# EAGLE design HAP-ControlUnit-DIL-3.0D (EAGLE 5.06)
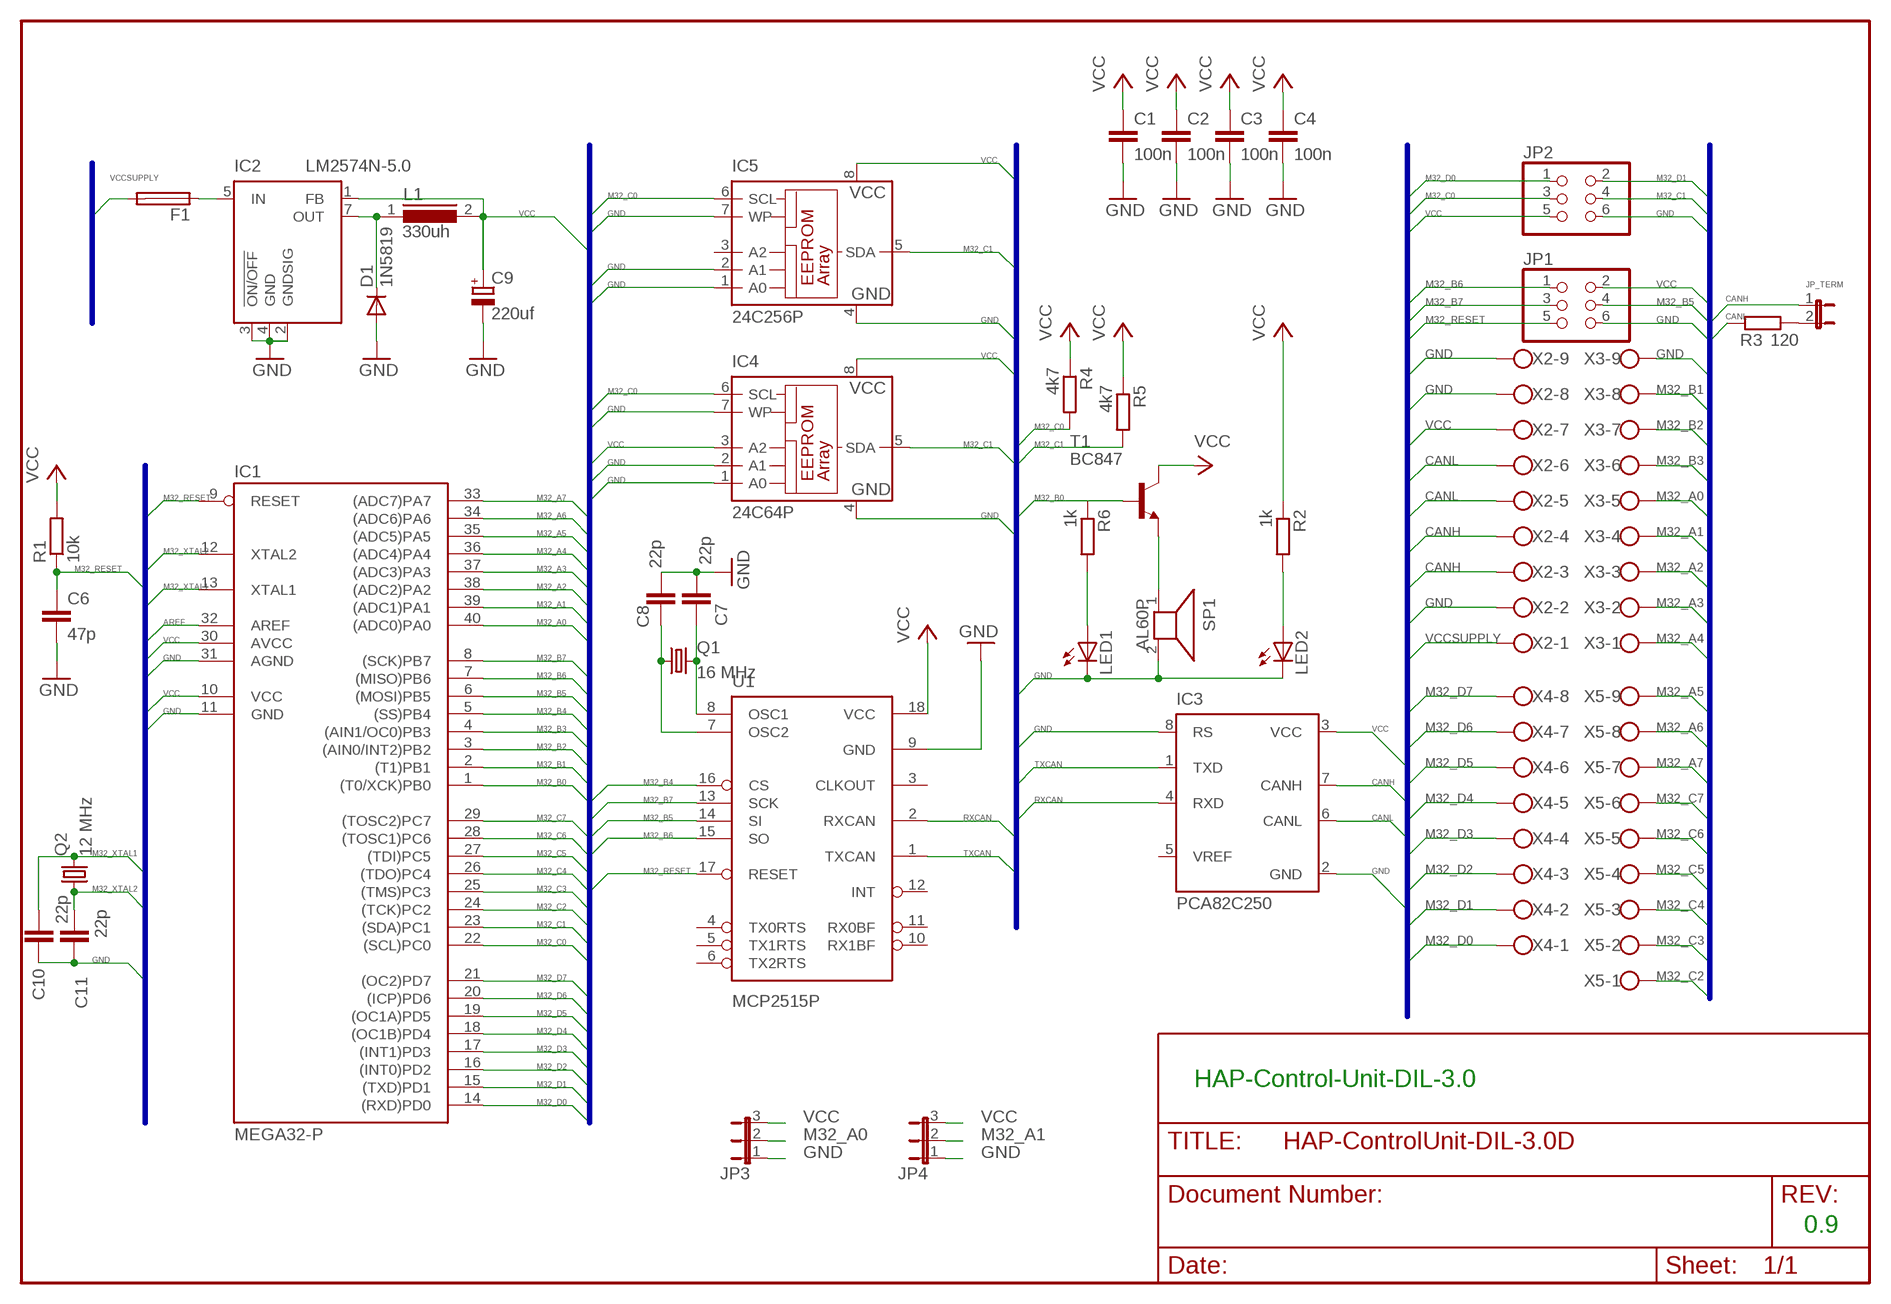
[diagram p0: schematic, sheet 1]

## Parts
C1  100n  C-EUC0805  [C0805]
C2  100n  C-EUC0805  [C0805]
C3  100n  C-EUC0805  [C0805]
C4  100n  C-EUC0805  [C0805]
C6  47p  C-EUC0805  [C0805]
C7  22p  C-EUC0805  [C0805]
C8  22p  C-EUC0805  [C0805]
C9  220uf  CPOL-EUE3.5-8  [E3,5-8]
C10  22p  C-EUC0805  [C0805]
C11  22p  C-EUC0805  [C0805]
D1  1N5819  1N4446  [DO35-10]
F1  TR5  [TR5]
IC1  MEGA32-P  [DIL40]
IC2  LM2574N-5.0  [DIL08]
IC3  PCA82C250  [DIL08]
IC4  24C64P  [DIL8]
IC5  24C256P  24C64P  [DIL8]
JP1  PINHD-2X3  [2X03]
JP2  PINHD-2X3  [2X03]
JP3  JP2E  [JP2]
JP4  JP2E  [JP2]
JP_TERM  JP1E  [JP1]
L1  330uh  82114R  [82114R]
LED1  LED3MM  [LED3MM]
LED2  LED3MM  [LED3MM]
Q1  16 MHz  CRYSTALHC49U70  [HC49U70]
Q2  12 MHz  CRYSTALHC49U70  [HC49U70]
R1  10k  R-EU_R0805  [R0805]
R2  1k  R-EU_R0805  [R0805]
R3  120  R-EU_R0805  [R0805]
R4  4k7  R-EU_R0805  [R0805]
R5  4k7  R-EU_R0805  [R0805]
R6  1k  R-EU_R0805  [R0805]
SP1  AL60P  [AL60P]
T1  BC847  [SOT23]
U1  MCP2515P  MCP2510P  [DIL18]
X2  W237-09P  [W237-9P]
X3  W237-09P  [W237-9P]
X4  W237-08P  [W237-8P]
X5  W237-09P  [W237-9P]

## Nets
AREF: IC1.32(AREF)
CANH: IC3.7(CANH) JP_TERM.1 X2.3 X2.4
CANL: IC3.6(CANL) R3.1 X2.5 X2.6
GND [VCC_GND]: C1.2 C2.2 C3.2 C4.2 C6.2 C7.2 C8.2 C9.- C10.2 C11.1 D1.A IC1.11(GND) IC1.31(AGND) IC2.2(GNDSIG) IC2.3(!ON/OFF) IC2.4(GND) IC3.2(GND) IC3.8(RS) IC4.1(A0) IC4.2(A1) IC4.4(GND) IC4.7(WP) IC5.1(A0) IC5.2(A1) IC5.4(GND) IC5.7(WP) JP1.6 JP2.6 JP3.1 JP4.1 LED1.K(C) LED2.K(C) SP1.2 U1.9(GND) X2.2 X2.8 X2.9 X3.9
M32_A0: IC1.40((ADC0)PA0) JP3.2 X3.5
M32_A1: IC1.39((ADC1)PA1) JP4.2 X3.4
M32_A2: IC1.38((ADC2)PA2) X3.3
M32_A3: IC1.37((ADC3)PA3) X3.2
M32_A4: IC1.36((ADC4)PA4) X3.1
M32_A5: IC1.35((ADC5)PA5) X5.9
M32_A6: IC1.34((ADC6)PA6) X5.8
M32_A7: IC1.33((ADC7)PA7) X5.7
M32_B0: IC1.1((T0/XCK)PB0) R6.1 T1.1(B)
M32_B1: IC1.2((T1)PB1) X3.8
M32_B2: IC1.3((AIN0/INT2)PB2) X3.7
M32_B3: IC1.4((AIN1/OC0)PB3) X3.6
M32_B4: IC1.5((SS)PB4) U1.16(CS)
M32_B5: IC1.6((MOSI)PB5) JP1.4 U1.14(SI)
M32_B6: IC1.7((MISO)PB6) JP1.1 U1.15(SO)
M32_B7: IC1.8((SCK)PB7) JP1.3 U1.13(SCK)
M32_C0: IC1.22((SCL)PC0) IC4.6(SCL) IC5.6(SCL) JP2.3 R4.2
M32_C1: IC1.23((SDA)PC1) IC4.5(SDA) IC5.5(SDA) JP2.4 R5.2
M32_C2: IC1.24((TCK)PC2) X5.1
M32_C3: IC1.25((TMS)PC3) X5.2
M32_C4: IC1.26((TDO)PC4) X5.3
M32_C5: IC1.27((TDI)PC5) X5.4
M32_C6: IC1.28((TOSC1)PC6) X5.5
M32_C7: IC1.29((TOSC2)PC7) X5.6
M32_D0: IC1.14((RXD)PD0) JP2.1 X4.1
M32_D1: IC1.15((TXD)PD1) JP2.2 X4.2
M32_D2: IC1.16((INT0)PD2) X4.3
M32_D3: IC1.17((INT1)PD3) X4.4
M32_D4: IC1.18((OC1B)PD4) X4.5
M32_D5: IC1.19((OC1A)PD5) X4.6
M32_D6: IC1.20((ICP)PD6) X4.7
M32_D7: IC1.21((OC2)PD7) X4.8
M32_RESET: C6.1 IC1.9(RESET) JP1.5 R1.1 U1.17(RESET)
M32_XTAL1: C10.1 IC1.13(XTAL1) Q2.2
M32_XTAL2: C11.2 IC1.12(XTAL2) Q2.1
N$1: LED1.A R6.2
N$2: D1.C IC2.7(OUT) L1.1
N$3: SP1.1 T1.2(E)
N$4: F1.1 IC2.5(IN)
N$5: C7.1 Q1.2 U1.8(OSC1)
N$6: JP_TERM.2 R3.2
N$7: C8.1 Q1.1 U1.7(OSC2)
N$16: LED2.A R2.2
RXCAN: IC3.4(RXD) U1.2(RXCAN)
TXCAN: IC3.1(TXD) U1.1(TXCAN)
VCC [VCC_GND]: C1.1 C2.1 C3.1 C4.1 C9.+ IC1.10(VCC) IC1.30(AVCC) IC2.1(FB) IC3.3(VCC) IC4.3(A2) IC4.8(VCC) IC5.8(VCC) JP1.2 JP2.5 JP3.3 JP4.3 L1.2 R1.2 R2.1 R4.1 R5.1 T1.3(C) U1.18(VCC) X2.7
VCCSUPPLY [VCC_GND]: F1.2 X2.1
Unconnected: IC3.5(VREF) IC5.3(A2) U1.3(CLKOUT) U1.4(TX0RTS) U1.5(TX1RTS) U1.6(TX2RTS) U1.10(RX1BF) U1.11(RX0BF) U1.12(INT)

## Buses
M32_RESET,M32_XTAL2,M32_XTAL1,M32_AREF,M32_AVCC,M32_AGND,M32_A[0..7],M32_B[0..7],M32_C[0..7],M32_D[0..7],VCC,GND,TXCAN,RXCAN,CANH,CANHB,CANL,CANLB,VCCSUPPLY,M32_XTAL1,M32_XTAL2,MCP_OSC1,MCP_OSC2,AREF

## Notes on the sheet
- HAP-Control-Unit-DIL-3.0
- 0.9

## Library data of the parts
C1-C4 C6-C8 C10 C11 = rcl:C-EU: CAPACITOR, European symbol
C9 = rcl:CPOL-EU: POLARIZED CAPACITOR, European symbol
D1 = diode:1N4446: DIODE
F1 = fuse:TR5: FUSE
IC1 = atmel:MEGA32-P: MICROCONTROLLER 32 Kbytes FLASH 2 Kbytes SRAM 1 Kbytes EEPROM USART 8-channel 10 bit ADC Source: www.atmel.com .. doc2503.pdf
IC2 = linear:LM2574?-*: SIMPLE SWITCHER 0.5A Step-Down Voltage Regulator Source: http://cache.national.com/ds/LM/LM2574.pdf
IC3 = micro-philips:PCA82C250: CAN CONTROLLER INTERFACE
IC4 IC5 = microchip:24*: Serial EEPROM I2C
JP1 JP2 = pinhead:PINHD-2X3: PIN HEADER
JP3 JP4 = jumper:JP2E: JUMPER
JP_TERM = jumper:JP1E: JUMPER
L1 = inductors:82114R: INDUCTOR
LED1 LED2 = led:LED: LED
Q1 Q2 = crystal:CRYSTAL: CRYSTAL
R1-R6 = rcl:R-EU_: RESISTOR, European symbol
SP1 = buzzer:AL60P: SPEAKER
T1 = transistor:BC847: NPN TRANSISTOR
U1 = microchip_can:MCP2510
X2 X3 X5 = con-wago-508:W237-09P: WAGO SREW CLAMP
X4 = con-wago-508:W237-08P: WAGO SREW CLAMP

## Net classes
1 VCC_GND: width 0.305 mm, clearance 0.203 mm

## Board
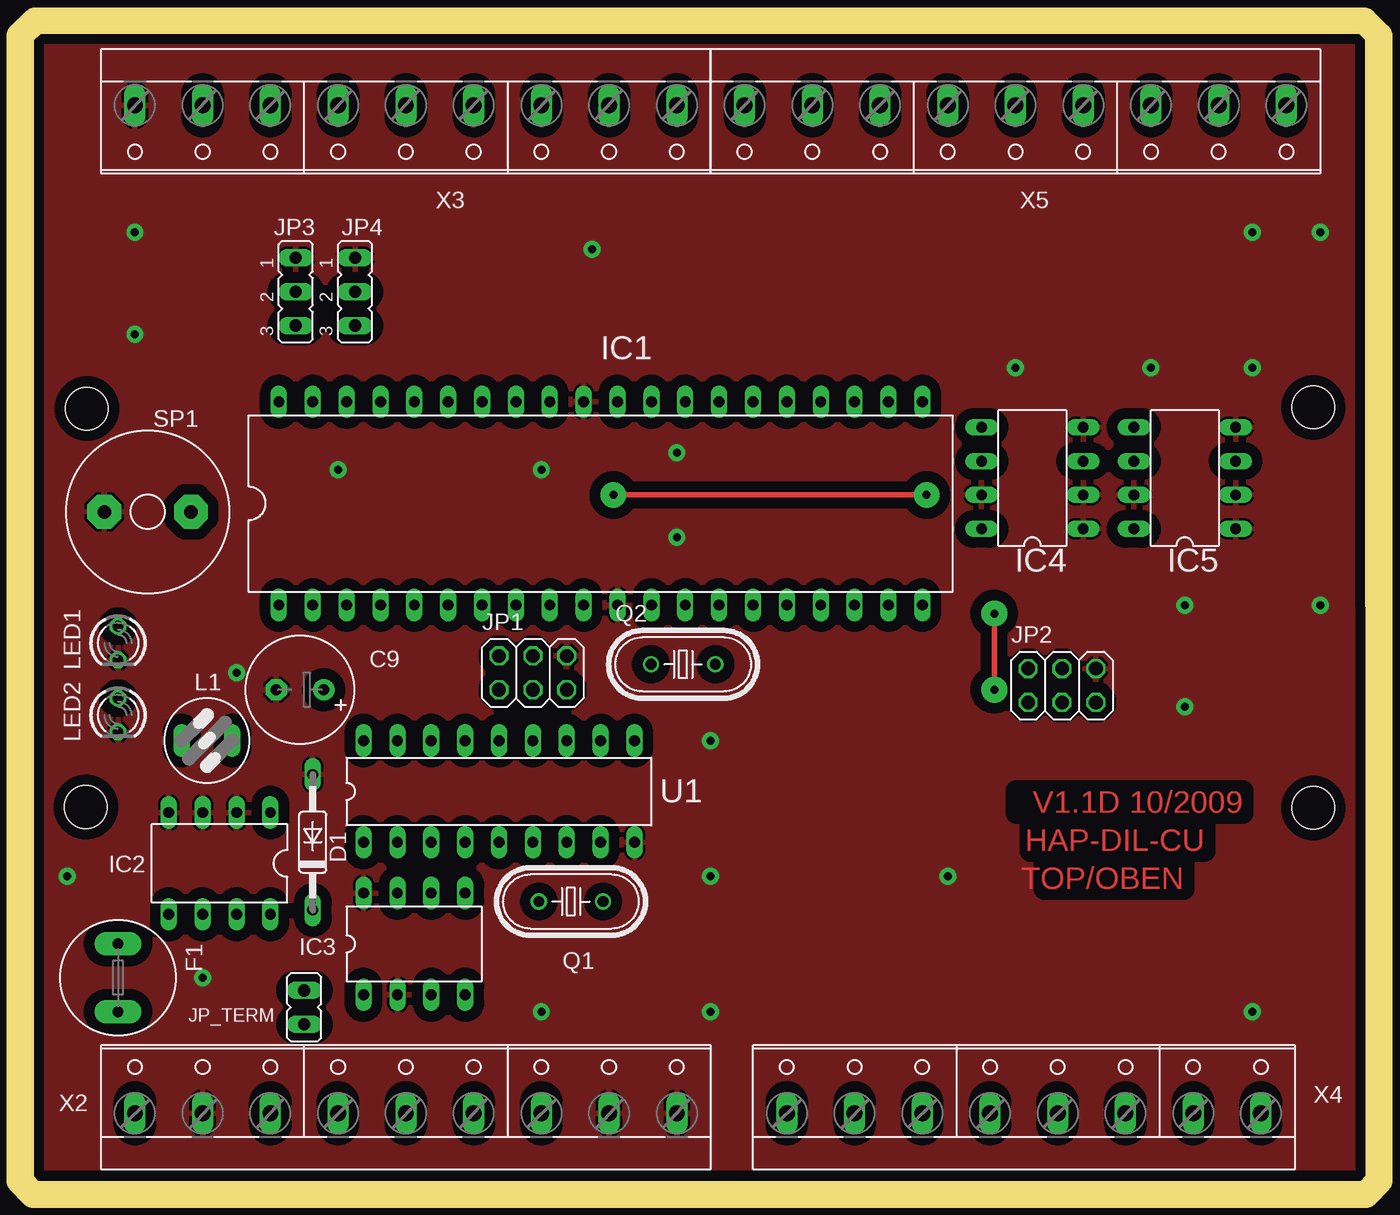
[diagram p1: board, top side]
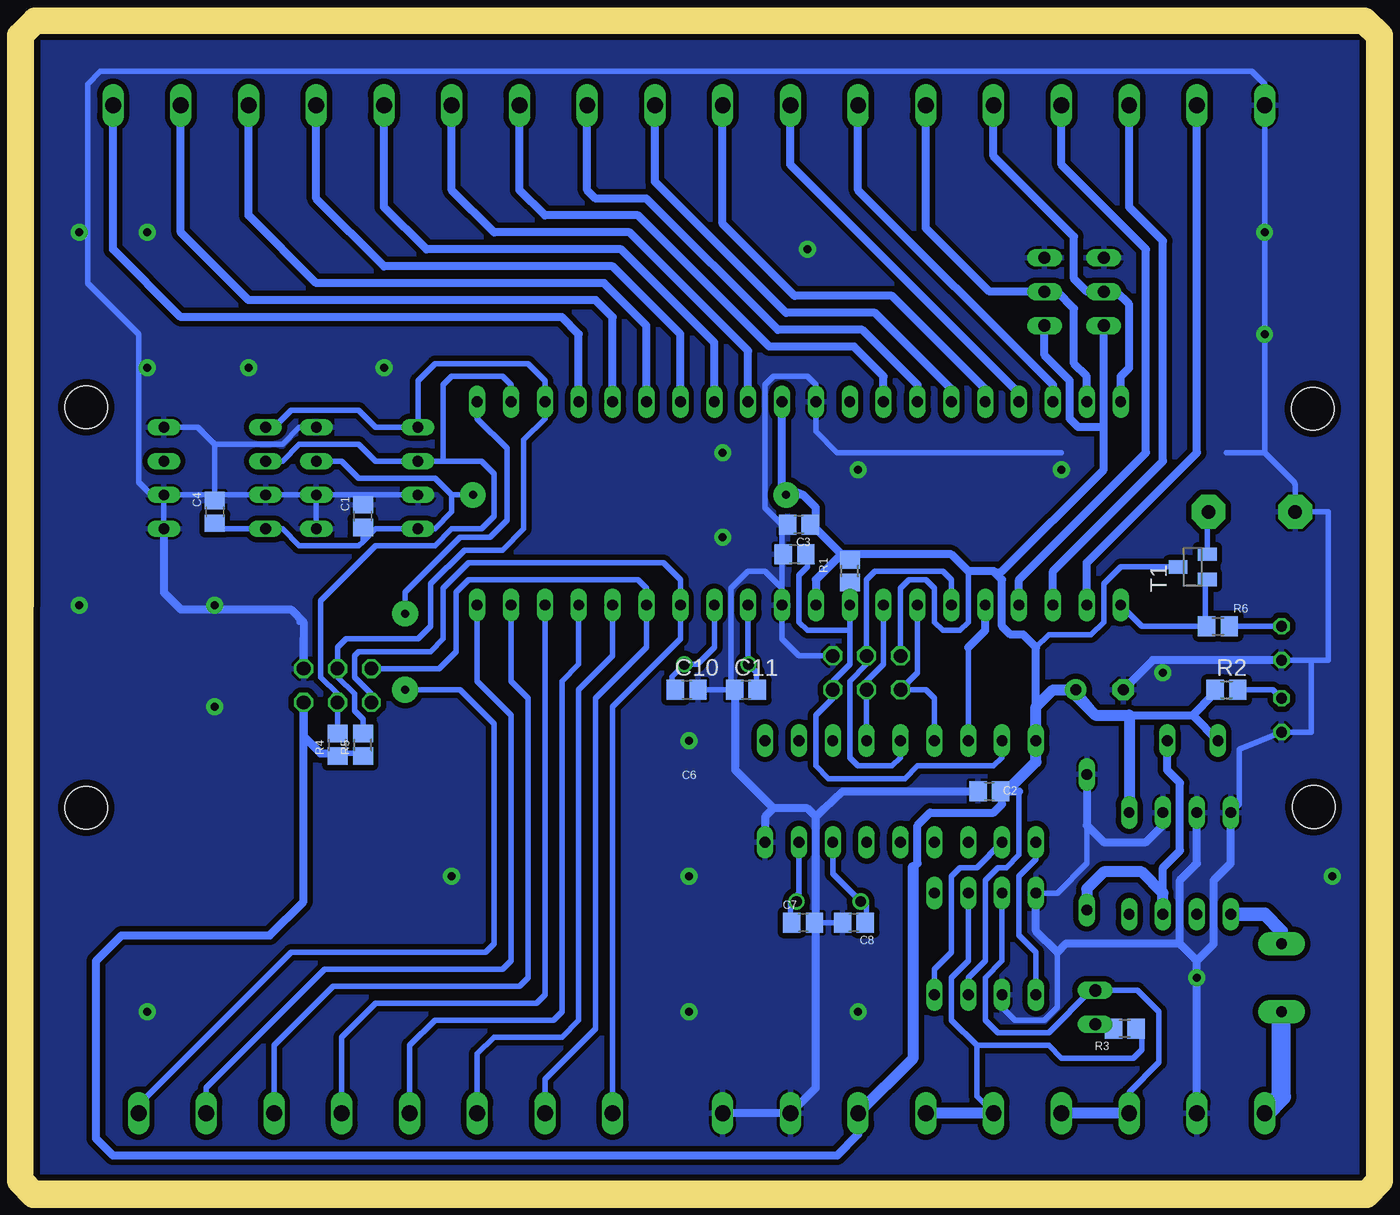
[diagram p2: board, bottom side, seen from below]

Size 99.97 x 86.08 mm. Coordinates in mm from the lower left corner, seen from the top.
Outline: 0.04,0 99.97,0 99.94,86.08 0,86.08 0,0.04
Copper layers (1*16): Top 0.035mm / dielectric 1.5mm / Bottom 0.035mm
Design rules "leiton *": minimum track width 6mil, minimum drill 12mil, track to track 16mil, track to pad 16mil, pad to pad 16mil, via to via 16mil, smd to smd 16mil, copper to edge 20mil, drill to drill 8mil, minimum pad ring 8mil, minimum via ring 6mil, stop-mask expansion 3mil, vias tented up to drill 0mil, thermal gap 8mil
Holes 3.2 mm at 4.01,57.94 96,28.01 3.94,28.07 96,58.04
Milling: 8 lines

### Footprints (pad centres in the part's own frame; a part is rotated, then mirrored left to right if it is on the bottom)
C0805 = smd 1.3 x 1.5: 1 -0.85,0; 2 0.85,0
E3,5-8 = drill 0.813 pad 1.6 round: + -1.778,0 | drill 0.813 pad 1.6 octagon: - 1.778,0
DO35-10 = drill 0.813 long: A 5.08,0; C -5.08,0
TR5 = drill 0.813 pad 1.778 long: 1 -2.54,0; 2 2.54,0
DIL40 = drill 0.813 long: 1 -24.13,-7.62; 2 -21.59,-7.62; 3 -19.05,-7.62; 4 -16.51,-7.62; 5 -13.97,-7.62; 6 -11.43,-7.62; 7 -8.89,-7.62; 8 -6.35,-7.62; 9 -3.81,-7.62; 10 -1.27,-7.62; 11 1.27,-7.62; 12 3.81,-7.62; 13 6.35,-7.62; 14 8.89,-7.62; 15 11.43,-7.62; 16 13.97,-7.62; 17 16.51,-7.62; 18 19.05,-7.62; 19 21.59,-7.62; 20 24.13,-7.62; 21 24.13,7.62; 22 21.59,7.62; 23 19.05,7.62; 24 16.51,7.62; 25 13.97,7.62; 26 11.43,7.62; 27 8.89,7.62; 28 6.35,7.62; 29 3.81,7.62; 30 1.27,7.62; 31 -1.27,7.62; 32 -3.81,7.62; 33 -6.35,7.62; 34 -8.89,7.62; 35 -11.43,7.62; 36 -13.97,7.62; 37 -16.51,7.62; 38 -19.05,7.62; 39 -21.59,7.62; 40 -24.13,7.62
DIL08 = drill 0.813 long: 1 -3.81,-3.81; 2 -1.27,-3.81; 3 1.27,-3.81; 4 3.81,-3.81; 5 3.81,3.81; 6 1.27,3.81; 7 -1.27,3.81; 8 -3.81,3.81
DIL8 = drill 0.813 long: 1 -3.81,-3.81; 2 -1.27,-3.81; 3 1.27,-3.81; 4 3.81,-3.81; 5 3.81,3.81; 6 1.27,3.81; 7 -1.27,3.81; 8 -3.81,3.81
2X03 = drill 1.016 octagon: 1 -2.54,-1.27; 2 -2.54,1.27; 3 0,-1.27; 4 0,1.27; 5 2.54,-1.27; 6 2.54,1.27
JP2 = drill 0.914 long: 1 -2.54,0; 2 0,0; 3 2.54,0
JP1 = drill 0.914 long: 1 0,-1.27; 2 0,1.27
82114R = drill 0.813 long: 1 0,1.905; 2 0,-1.905
LED3MM = drill 0.813 octagon: A -1.27,0; K 1.27,0
HC49U70 = drill 0.813 round: 1 -2.413,0; 2 2.413,0
R0805 = smd 1.3 x 1.5: 1 -0.85,0; 2 0.85,0
AL60P = drill 1.016 pad 2.54 octagon: 1 -3.251,0; 2 3.251,0
SOT23 = smd 1 x 1.4: 1 -0.95,-1.1; 2 0.95,-1.1; 3 0,1.1
DIL18 = drill 0.813 long: 1 -10.16,-3.81; 2 -7.62,-3.81; 3 -5.08,-3.81; 4 -2.54,-3.81; 5 0,-3.81; 6 2.54,-3.81; 7 5.08,-3.81; 8 7.62,-3.81; 9 10.16,-3.81; 10 10.16,3.81; 11 7.62,3.81; 12 5.08,3.81; 13 2.54,3.81; 14 0,3.81; 15 -2.54,3.81; 16 -5.08,3.81; 17 -7.62,3.81; 18 -10.16,3.81
W237-9P = drill 1.194 long: 1 -20.32,-0.635; 2 -15.24,-0.635; 3 -10.16,-0.635; 4 -5.08,-0.635; 5 0,-0.635; 6 5.08,-0.635; 7 10.16,-0.635; 8 15.24,-0.635; 9 20.32,-0.635
W237-8P = drill 1.194 long: 1 -17.78,-0.635; 2 -12.7,-0.635; 3 -7.62,-0.635; 4 -2.54,-0.635; 5 2.54,-0.635; 6 7.62,-0.635; 7 12.7,-0.635; 8 17.78,-0.635

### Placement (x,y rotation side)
C1  75.25,49.88 90 bottom
C2  28.26,29.25 180 bottom
C3  42.55,49.25 180 bottom
C4  86.36,50.2 90 bottom
C6  42.86,47.02 180 bottom
C7  42.23,19.4 0 bottom
C8  38.42,19.4 180 bottom
C9  20,36.86 180 top
C10  50.96,36.86 0 bottom
C11  46.51,36.86 0 bottom
D1  20.95,25.43 90 top
F1  6.35,15.28 270 top
IC1  42.55,50.83 0 top
IC2  13.97,23.85 180 top
IC3  28.57,17.82 0 top
IC4  74.93,52.74 90 top
IC5  86.36,52.74 90 top
JP1  37.47,38.13 0 top
JP2  77.15,37.18 0 top
JP3  19.68,66.71 270 top
JP4  24.13,66.71 270 top
JP_TERM  20.32,13.05 180 top
L1  13.02,33.05 270 top
LED1  6.35,40.36 270 top
LED2  6.35,34.96 270 top
Q1  40.32,20.99 0 top
Q2  48.74,38.77 0 top
R1  38.73,45.75 90 bottom
R2  10.48,36.86 0 bottom
R3  18.1,11.46 180 bottom
R4  77.15,32.74 90 bottom
R5  75.25,32.74 90 bottom
R6  11.11,41.63 0 bottom
SP1  8.57,50.2 180 top
T1  13.02,46.07 90 bottom
U1  34.92,29.25 0 top
X2  27.94,5.75 0 top
X3  27.94,80.05 180 top
X4  74.3,5.75 0 top
X5  73.66,80.05 180 top

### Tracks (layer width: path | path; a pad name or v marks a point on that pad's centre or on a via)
CANH
  Bottom 0.406: IC3.7 27.3,16.55 28.57,15.28 28.57,12.1 27.62,11.15 23.81,11.15 20.64,14.32 JP_TERM.1 17.14,14.32 15.56,12.73 15.56,8.93 17.78,6.7 X2.3
  Bottom 0.813: X2.3 X2.4
CANL
  Bottom 0.406: IC3.6 29.84,16.55 31.11,15.28 31.11,12.1 29.21,10.2 | 29.21,10.2 23.81,10.2 22.86,9.24 17.46,9.24 16.83,9.88 16.83,11.36 R3.1 | X2.5 29.21,6.38 29.21,10.2
  Bottom 0.813: X2.5 X2.6
GND  (via drill 0.6 pad 1.27)
  Bottom 0.406: JP1.6 42.55,39.4 43.81,40.67 IC1.11 43.81,44.48 | 43.81,49.25 45.09,50.52 45.09,59.72 44.45,60.36 41.91,60.36 41.27,59.72 IC1.31 41.27,56.23 39.69,54.64 22.86,54.64 | 43.81,44.48 43.81,48.61 | 43.81,48.61 43.81,49.25 | C11.1 47.62,36.86 | 47.62,36.86 C10.2 | 47.62,36.86 47.62,44.48 46.35,45.75 45.09,45.75 43.81,44.48 | IC4.4 80.01,56.55 81.28,55.28 86.36,55.28 | 86.36,55.28 87.63,56.55 IC5.4 | 75.25,51.47 IC4.7 IC5.2 | 75.25,51.47 IC4.2 | IC4.2 IC5.7 86.36,51.47 | IC5.2 86.36,51.47 | 86.36,51.47 86.36,55.28 | IC5.2 IC5.1 | IC4.2 IC4.1 | 41.59,19.4 C7.2 C8.2 | SP1.2 2.86,50.2 2.86,39.09 LED1.K 4.13,39.09 4.13,33.69 LED2.K 9.53,32.42 9.53,28.29 IC2.4 | 7.62,54.64 X3.9 | SP1.2 5.08,50.2 | 43.81,49.25 C3.2 | C6.2 43.81,47.13 43.81,48.61 | 75.25,51.47 C1.2 | 86.36,51.47 C4.2 | IC5.2 91.12,51.47 92.08,52.42 92.08,63.53 95.89,67.34 95.89,82.27 94.93,83.22 8.57,83.22 7.62,82.27 X3.9 | X3.9 7.94,80.36 | 7.62,54.64 10.48,54.64 | SP1.2 5.32,52.18 5.4,52.42 7.62,54.64 | 79.69,41.94 80.01,41.94 | IC3.2 27.3,13.05 26.35,12.1 24.13,12.1 23.18,13.05 23.18,17.18 | IC3.8 23.18,21.62 20.95,23.85 D1.A
  Bottom 0.61: 41.59,19.4 41.27,19.72 41.27,27.34 | 41.27,27.34 41.91,27.98 44.45,27.98 | 44.45,27.98 45.09,27.34 U1.9 | C2.2 39.27,29.25 40.64,27.98 41.27,27.34 | X2.8 42.86,5.12 | X2.8 X2.9 | C7.2 41.27,19.3 41.27,7.02 X2.8 | C11.1 47.31,36.86 47.31,30.83 44.45,27.98 | IC5.1 90.17,44.17 88.9,42.9 80.64,42.9 79.69,41.94 JP2.6 79.69,40.67 | X2.2 12.7,16.55 | 12.7,16.55 11.43,17.82 11.43,22.58 10.16,23.85 IC2.4 | IC2.3 12.7,23.85 13.97,22.58 13.97,17.82 | 12.7,16.55 13.97,17.82 | C9.- 16,39.09 LED1.K | IC2.2 15.24,26.71 16.51,25.43 19.68,25.43 20.95,26.71 D1.A | 13.97,17.82 22.54,17.82 23.18,17.18 24.77,18.77 IC3.8
  Bottom 1.422: X2.2 12.7,5.43
  other vias: 22.86,53.38 38.1,53.38 48.26,54.64 48.26,48.29 50.8,33.05 50.8,22.89 50.8,12.73 38.1,12.73 12.7,15.28 2.54,22.89 15.24,38.13 68.58,22.89 91.44,12.73 86.36,35.59 86.36,43.21 96.52,43.21 73.66,60.99 83.82,60.99 91.44,60.99 41.91,69.88 96.52,71.16 91.44,71.16 7.62,63.53 7.62,71.16
  pour Bottom: 0,0.04 100.01,0.04 100.01,86.08 0,86.08
  pour Top (isolate 0.813): 0,0.04 100.01,0.04 100.01,86.08 0,86.08
M32_A0
  Bottom 0.406: 18.73,66.71 JP3.2 20.95,66.71
  Bottom 0.61: 27.94,80.36 X3.5 | 27.94,80.36 27.94,79.41 | IC1.40 18.41,60.36 17.78,60.99 17.78,65.76 18.73,66.71 | 20.95,66.71 21.91,67.66 21.91,70.84 27.94,76.87 27.94,80.36
M32_A1
  Bottom 0.61: IC1.39 20.95,59.72 20.95,60.36 21.91,61.31 21.91,65.44 23.18,66.71 JP4.2 28.26,66.71 33.02,71.47 X3.4
M32_A2
  Bottom 0.61: X3.3 38.1,74.33 23.5,59.72 IC1.38
M32_A3
  Bottom 0.61: X3.2 43.18,76.23 26.04,59.09 IC1.37
M32_A4
  Bottom 0.61: IC1.36 28.57,59.41 35.56,66.39 42.86,66.39 48.26,71.79 X3.1
M32_A5
  Bottom 0.61: X5.9 53.34,74.97 43.5,65.12 36.83,65.12 31.11,59.41 IC1.35
M32_A6
  Bottom 0.61: IC1.34 33.66,59.72 37.78,63.85 44.13,63.85 53.98,73.69 57.78,73.69 58.42,74.33 X5.8
M32_A7
  Bottom 0.61: X5.7 63.5,74.33 61.59,72.42 54.61,72.42 44.77,62.58 38.42,62.58 36.2,60.36 IC1.33
M32_B0
  Bottom 0.406: R6.1 12.06,41.73 12.06,42.58 | T1.1 12.06,45.12 12.06,42.58 | 12.06,42.58 12.06,41.63 16.83,41.63 IC1.1
M32_B1
  Bottom 0.61: IC1.2 20.95,46.39 12.7,54.64 X3.8
M32_B2
  Bottom 0.61: IC1.3 23.5,45.75 15.24,54.01 15.24,70.52 17.78,73.06 X3.7
M32_B3
  Bottom 0.61: IC1.4 26.04,45.12 16.51,54.64 16.51,69.88 22.86,76.23 X3.6
M32_B4
  Bottom 0.406: U1.16 29.84,40.04
  Bottom 0.61: IC1.5 28.57,41.31 29.84,40.04
M32_B5
  Bottom 0.406: IC1.6 31.11,45.12 31.75,45.75 36.83,45.75 37.47,45.12 JP1.4 37.47,38.77 38.73,37.5 38.73,31.79 38.1,31.15 35.56,31.15 34.92,31.79 U1.14
M32_B6
  Bottom 0.406: IC1.7 33.66,38.13 JP1.1 33.02,36.86 32.38,36.23 U1.15
M32_B7
  Bottom 0.406: IC1.8 36.2,38.77 37.47,37.5 JP1.3 U1.13
M32_C0
  Bottom 0.406: IC1.22 64.14,59.72 64.77,60.36 68.58,60.36 69.22,59.72 69.22,54.01 IC4.6 | IC4.6 74.3,54.01 75.56,55.28 80.01,55.28 81.28,54.01 IC5.6 | IC4.6 66.36,54.01 65.41,53.06 65.41,49.88 66.36,48.93 68.58,48.93 69.85,47.66 74.3,47.66 78.42,43.53 78.42,37.82 77.15,36.55 JP2.3 R4.2
M32_C1
  Bottom 0.406: IC5.5 81.92,56.55 80.64,57.82 75.56,57.82 74.3,56.55 IC4.5 71.12,60.04 69.85,61.31 62.87,61.31 61.59,60.04 IC1.23 61.59,57.18 63.18,55.6 63.18,48.93 64.77,47.34 67.63,47.34 70.17,44.8 70.17,41.63 71.12,40.67 76.52,40.67 77.15,40.04 JP2.4 77.15,37.82 75.88,36.55 75.88,35.28 75.25,34.64 R5.2
M32_C2
  Bottom 0.61: IC1.24 59.05,63.53 60.33,64.8 88.9,64.8 93.98,69.88 X5.1
M32_C3
  Bottom 0.61: IC1.25 56.52,64.8 57.78,66.08 83.82,66.08 88.9,71.16 X5.2
M32_C4
  Bottom 0.61: IC1.26 53.98,64.17 57.15,67.34 78.74,67.34 83.82,72.42 X5.3
M32_C5
  Bottom 0.61: IC1.27 51.44,63.53 56.52,68.61 73.66,68.61 78.74,73.69 X5.4
M32_C6
  Bottom 0.61: IC1.28 48.9,62.9 55.88,69.88 70.48,69.88 73.66,73.06 X5.5
M32_C7
  Bottom 0.61: IC1.29 46.35,62.26 55.24,71.16 65.41,71.16 68.58,74.33 X5.6
M32_D0
  Bottom 0.406: X4.1 56.52,35.59 51.44,40.67 IC1.14 51.44,45.12 52.7,46.39 67.31,46.39 69.22,44.48 69.22,40.67 70.17,39.72 75.56,39.72 75.88,39.4 75.88,37.82 74.61,36.55 JP2.1
M32_D1
  Bottom 0.406: JP2.2 69.53,38.45 68.26,39.72 68.26,44.17 67.63,44.8 67.31,45.12 54.61,45.12 53.98,44.48 IC1.15 53.98,40.04 57.78,36.23 57.78,11.46 61.59,7.66 X4.2
M32_D2
  Bottom 0.406: IC1.16 56.52,39.4 59.05,36.86 59.05,12.1 60.33,10.83 65.41,10.83 66.67,9.56 X4.3
M32_D3
  Bottom 0.406: IC1.17 59.05,38.77 60.33,37.5 60.33,12.73 60.96,12.1 69.85,12.1 71.75,10.2 X4.4
M32_D4
  Bottom 0.406: IC1.18 61.59,14.01 62.23,13.37 74.3,13.37 76.83,10.83 X4.5
M32_D5
  Bottom 0.406: IC1.19 64.14,37.5 62.87,36.23 62.87,15.28 63.5,14.64 77.47,14.64 81.92,10.2 X4.6
M32_D6
  Bottom 0.406: IC1.20 66.67,37.5 64.14,34.96 64.14,16.55 64.77,15.91 78.11,15.91 87,7.02 X4.7
M32_D7  (via drill 0.6 pad 1.93)
  Top 0.406: v72.07,36.86 v72.07,42.58
  Bottom 0.406: X4.8 92.08,5.75 80.64,17.18 66.04,17.18 65.41,17.82 65.41,34.32 67.94,36.86 v72.07,36.86 | IC1.21 66.67,57.18 64.45,54.96 64.45,49.56 65.72,48.29 67.94,48.29 72.07,44.17 v72.07,42.58
M32_RESET
  Bottom 0.406: 38.73,41.31 38.73,38.77 40.01,37.5 JP1.5 40.01,36.23 41.27,34.96 41.27,31.15 40.32,30.2 35.24,30.2 34.61,30.2 33.66,31.15 27.94,31.15 27.3,31.79 U1.17 | 38.73,41.31 IC1.9 R1.1 | C6.1 41.91,46.92 41.91,46.07 42.55,45.44 42.55,41.94 41.91,41.31 38.73,41.31
M32_XTAL1
  Bottom 0.406: IC1.13 48.9,40.04 50.16,38.77 Q2.2 52.07,37.85 52.07,36.86 C10.1
M32_XTAL2
  Bottom 0.406: IC1.12 46.35,38.77 Q2.1 45.72,38.17 45.72,36.86 C11.2
N$1
  Bottom 0.406: R6.2 9.95,41.94 10.16,41.63 LED1.A
N$2
  Bottom 0.61: IC2.7 15.24,23.53 13.97,24.8 13.97,29.88 14.92,30.83 L1.1
  Bottom 0.813: IC2.7 15.24,21.62 16.83,23.21 19.68,23.21 20.95,21.94 D1.C
N$3
  Bottom 0.406: SP1.1 11.75,50.2 11.92,49.39 T1.2
N$4
  Bottom 1.016: F1.1 6.35,18.77 7.62,20.04 IC2.5
N$5
  Bottom 0.406: 42.55,21.18 Q1.2 42.86,20.99 43.18,20.67 43.18,19.5 | C7.1 43.18,19.5 | 43.18,19.5 43.18,20.99 42.55,21.62 U1.8
N$6
  Bottom 0.406: R3.2 19.27,11.15 19.37,11.78 JP_TERM.2
N$7
  Bottom 0.406: C8.1 37.47,19.5 37.47,20.67 37.78,20.99 Q1.1 40.01,23.09 U1.7
N$16
  Bottom 0.406: LED2.A 6.99,36.86 R2.2
RXCAN
  Bottom 0.406: IC3.4 32.38,15.91 31.11,17.18 31.11,22.89 30.48,23.53 29.21,23.53 U1.2
TXCAN
  Bottom 0.406: IC3.1 24.77,17.18 26.04,18.45 26.04,22.89 24.77,24.16 U1.1
VCC  (via drill 0.6 pad 1.93)
  Top 0.406: v43.5,51.47 v66.99,51.47
  Bottom 0.406: 29.84,45.75 29.84,41.94 30.48,41.31 31.75,41.31 32.38,41.94 32.38,44.48 33.02,45.12 34.29,45.12 34.92,44.48 JP1.2 | 43.18,51.47 43.81,52.1 v43.5,51.47 | 41.27,48.93 41.27,49.25 C3.1 | IC4.3 76.83,54.01 75.56,52.74 69.85,52.74 68.58,51.47 | 68.58,51.47 68.58,50.2 69.85,48.93 IC4.8 74.3,48.93 75.25,47.98 | 75.25,47.98 75.56,47.66 80.01,47.66 81.28,48.93 IC5.8 85.94,48.93 C4.1 | R5.1 75.46,32.1 77.15,32.1 R4.1 77.37,32.1 77.47,32.1 | IC3.3 29.84,15.28 28.57,16.55 28.57,22.58 27.62,23.53 26.99,23.53 26.04,24.48 26.04,29.25 | 38.73,47.02 R1.2 | 75.25,47.98 C1.1 | v66.99,51.47 68.58,51.47 | T1.3 18.41,46.07 19.68,44.8 19.68,41.94 20.64,40.99 23.81,40.99 24.77,40.04 | 11.43,36.55 R2.1 | 27.94,45.75 27.3,45.75
  Bottom 0.61: IC1.10 41.27,45.12 39.37,47.02 | 39.37,47.02 38.73,47.02 31.11,47.02 29.84,45.75 27.94,45.75 27.3,45.12 27.3,41.63 26.67,40.99 25.72,40.99 24.77,40.04 U1.18 | 42.23,51.47 43.18,51.47 | IC1.30 43.81,52.1 42.23,51.47 | 42.23,51.47 41.27,50.52 41.27,49.25 | 39.37,47.02 41.27,48.93 | 26.04,29.25 27.3,29.25 27.3,28.29 27.94,27.66 32.7,27.66 33.66,26.71 33.66,23.85 33.97,23.53 | X2.7 38.1,3.53 39.69,1.94 93.98,1.94 95.25,3.21 95.25,16.55 93.34,18.45 82.23,18.45 79.69,20.99 JP2.5 79.69,33.37 78.42,32.1 77.47,32.1 | 13.02,34.96 11.43,36.55 | C9.+ 20.19,34.96 17.78,34.96 13.02,34.96 | 13.02,34.96 L1.2 | C9.+ 21.59,36.86 | C9.+ 21.91,36.86 20.32,34.96 | 19.68,56.55 JP3.3 | JP4.3 24.13,61.95 22.23,60.04 22.23,57.18 21.59,56.55 19.68,56.55 | 19.68,56.55 19.68,53.38 27.3,45.75
  Bottom 0.813: X2.7 33.97,9.24 33.97,23.53 | IC2.1 17.78,34.96 20.32,34.96 21.91,36.55 21.91,36.86 23.5,36.86 24.77,35.59 U1.18 24.77,31.47 26.99,29.25 27.3,29.25 C2.1
VCCSUPPLY
  Bottom 0.813: 6.35,6.38 6.35,10.51
  Bottom 1.422: X2.1 6.35,6.38 F1.2

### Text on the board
Top: V1.1D 10/2009 | HAP-DIL-CU | TOP/OBEN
